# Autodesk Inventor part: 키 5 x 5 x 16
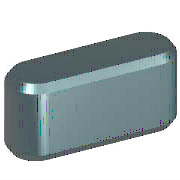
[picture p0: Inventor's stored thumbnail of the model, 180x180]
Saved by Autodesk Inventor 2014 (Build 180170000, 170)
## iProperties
IsCustomPart: 1
Created: 2012-02
Part Number: 키 5 x 5 x 16
Material: 강철, 연강
Description: 키 및 해당 키홈
Document SubType Name: Modeling
Standard: KS B 1311
Designer: mduedu
Standards Organization: KS
Language: ko-KR
Size Designation: 5 x 5 x 16
Categories: <MemberInstance><Categories><Category DisplayName="샤프트 부품" InternalName="7f7aeb1f-a693-4053-b835-cee3144e0d98" Mnemonic="SHFT"><Category DisplayName="키" Interna
Density: 1 g/cm^3
Appearance: 노란색
Author: mduedu
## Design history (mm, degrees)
workplane "Work Plane1"
workplane "Work Plane2"
sketch "스케치1"
  geometry: L1 (2.5, 2.5)-(13.5, 2.5); L2 (13.5, -2.5)-(2.5, -2.5); L3 (0, 9.4)-(0, -7.4) reference; L4 (-5, 0)-(30, 0) reference; L5 (16, 0)-(16, 7); A1 r 2.5 centre (2.5, 0) between (2.5, 2.5) and (2.5, -2.5); A2 r 2.5 centre (13.5, 0) between (13.5, -2.5) and (13.5, 2.5)
  constraints: 6 end point, 5 point on circle, 4 tangent, 3 point on line, 2 centre point, 1 horizontal, 1 parallel, 1 perpendicular
  dimensions: "d0" = 2.5 radius of A1 (= 0.5 x PB); "d13" = 2.5 radius of A2 (= 0.5 x PB); "d14" = 16 distance between parallel lines of L5 L3 (= NLG)
extrude "본체1" new body sketch "스케치1" taper "d3" = 0 deg; stored distance "d4" = 10
workplane "Work Plane3"
body "Solid1"
chamfer "모따기1" distance "d8" = 0.4 (= PHH); stored, may be unused: second distance "d9" = 0.4 (= PHH), angle "d15" = 45 deg
other parameters: "d1" = -3 (= -PNT), "d2" = 2 (= PH - PNT), "NLG" = 16 [user parameter; used in 3 equation terms], "PB" = 5 [user parameter; used in 2 equation terms], "PNT" = 3 [user parameter; used in 2 equation terms], "PH" = 5 [user parameter; used in 1 equation term], "PHH" = 0.4 [user parameter; used in 2 equation terms], "d10" = 0, "d16" = 0, "d17" = 0, "d18" = 0, "WDMIN" = 12 [user parameter], "PLB2" = 16 (= NLG) [user parameter], "WDMAX" = 17 [user parameter], "PLB1" = 16 (= NLG) [user parameter], "RR" = 0.16 [user parameter], "PUEB" = 2.3 [user parameter]
